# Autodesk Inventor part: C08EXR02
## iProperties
Created: 2009-06
Part Number: C08EXR02
Document SubType Name: Modeling
Designer: Sham
Density: 1 g/cm^3
Author: Sham
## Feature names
1. Loft1
2. Shell1
3. Extrusion1
4. Fillet1
5. Extrusion2
6. Fillet2
7. Hole1
8. Rectangular Pattern1
9. Hole2
10. Rectangular Pattern2
